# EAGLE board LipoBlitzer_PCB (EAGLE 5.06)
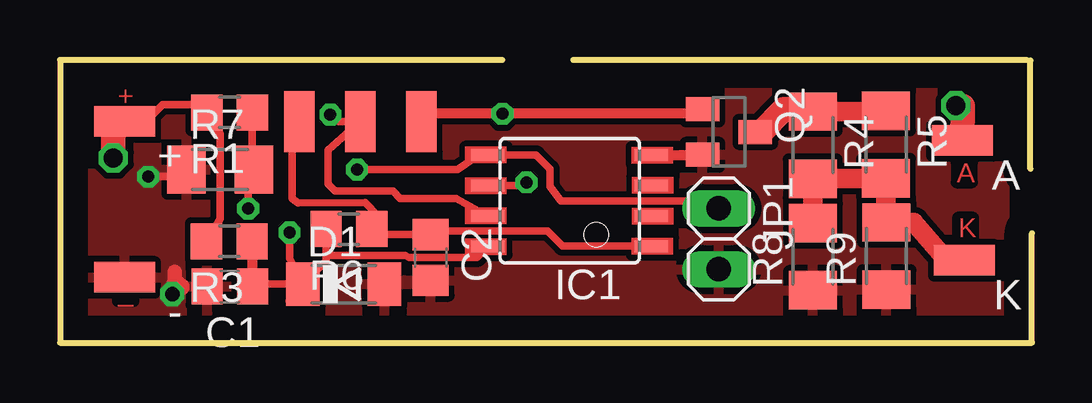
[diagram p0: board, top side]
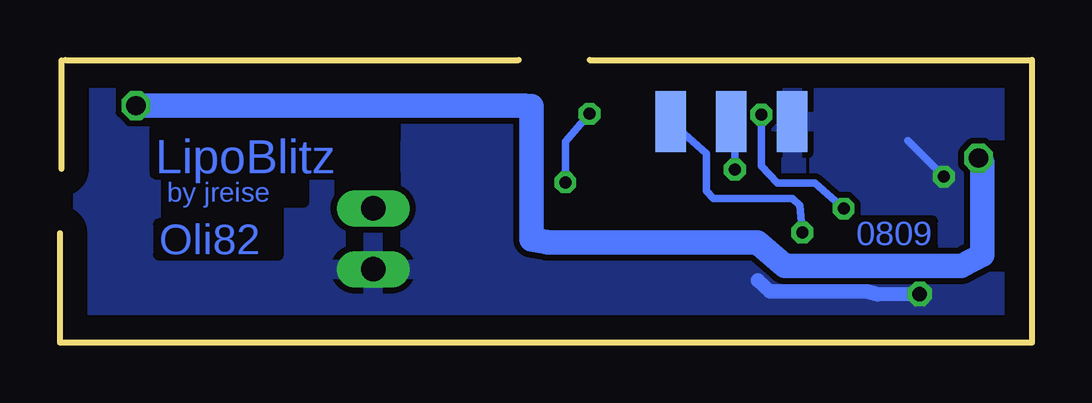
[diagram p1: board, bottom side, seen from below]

Size 40.52 x 11.8 mm. Coordinates in mm from the lower left corner, seen from the top.
Outline: 40.51,0 0,0 0,11.8
Outline: 40.29,11.8 21.4,11.8
Outline: 40.52,0.04 40.52,4.56
Outline: 18.44,11.8 0.01,11.8
Outline: 40.45,7.26 40.45,11.78
Copper layers (1*16): Top 0.035mm / dielectric 1.5mm / Bottom 0.035mm
Design rules "default": minimum track width 10mil, minimum drill 24mil, track to track 8mil, track to pad 8mil, pad to pad 8mil, via to via 8mil, smd to smd 8mil, copper to edge 40mil, drill to drill 8mil, minimum pad ring 10mil, minimum via ring 8mil, stop-mask expansion 4mil, vias tented up to drill 0mil, thermal gap 10mil

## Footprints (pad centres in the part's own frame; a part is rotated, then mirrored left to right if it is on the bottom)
SMD1,27-2,54 = smd 1.27 x 2.54: 1 0,0
C0805 = smd 1.3 x 1.5: 1 -0.95,0; 2 0.95,0
SOD80C = smd 1.4 x 1.8: A 1.7,0; C -1.7,0
8S2 = smd 0.5 x 1.4: 1 -1.905,-3.404; 2 -0.645,-3.404; 3 0.625,-3.404; 4 1.895,-3.404; 5 1.905,3.404; 6 0.635,3.404; 7 -0.635,3.404; 8 -1.905,3.404
1X02 = drill 1.016 long: 1 -1.27,0; 2 1.27,0
SOT23 = smd 1 x 1.4: 1 -0.95,-1.1; 2 0.95,-1.1; 3 0,1.1
R0805 = smd 1.3 x 1.5: 1 -0.95,0; 2 0.95,0
M1206 = smd 1.6 x 2: 1 -1.4,0; 2 1.4,0
MA03-2EDGE = smd 2.54 x 1.27: 1 0,0; 3 0,2.54; 5 0,5.08 | smd 2.54 x 1.27 bottom: 2 0,0; 4 0,2.54; 6 0,5.08

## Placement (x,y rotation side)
+  WIREPADSMD1,27-254  [SMD1,27-2,54]  2.7,9.25 90 top
-  WIREPADSMD1,27-254  [SMD1,27-2,54]  2.7,2.74 90 top
A  WIREPADSMD1,27-254  [SMD1,27-2,54]  37.62,8.44 90 top
C1  100µF  [C0805]  7.09,2.35 180 top
C2  100µF  [C0805]  15.46,3.56 270 top
D1  Z 5.1  [SOD80C]  11.83,2.45 0 top
IC1  TINY13-20SU  [8S2]  21.24,5.93 90 top
JP1  [1X02]  27.46,4.34 270 top
K  WIREPADSMD1,27-254  [SMD1,27-2,54]  37.7,3.44 90 top
Q2  IRLML2502  [SOT23]  27.89,8.8 270 top
R1  68k  [R0805]  7.07,9.61 180 top
R3  4k7  [R0805]  7.06,4.24 180 top
R4  30R  [M1206]  31.38,8.25 270 top
R5  30R  [M1206]  34.43,8.27 270 top
R6  10k  [R0805]  12.05,4.74 180 top
R7  4k7  [M1206]  6.68,7.23 0 top
R8  200R  [M1206]  31.39,3.59 90 top
R9  200R  [M1206]  34.45,3.62 90 top
U$1  MA02-3  [MA03-2EDGE]  15.07,9.22 90 top

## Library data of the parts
+ - A K = wirepad
C1 C2 R1 R3-R9 = rcl
D1 = diode
IC1 = atmel
JP1 = pinhead
Q2 = transistor-small-signal
U$1 = akku

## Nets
GND: -.1 C1.2 C2.2 D1.A IC1.4 JP1.2 Q2.2 R7.1 R8.1 R9.1 U$1.6
N$2: IC1.5 JP1.1 U$1.4
N$3: C1.1 D1.C IC1.8 R3.1 R6.2 U$1.2
N$4: Q2.3 R4.1 R5.1
N$5: IC1.6 Q2.1 U$1.1
N$7: K.1 R4.2 R5.2 R8.2 R9.2
N$10: IC1.7 R1.1 R7.2 U$1.3
N$11: C2.1 IC1.1 R6.1 U$1.5
VCC: +.1 A.1 R1.2 R3.2

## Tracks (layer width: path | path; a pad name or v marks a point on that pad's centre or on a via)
GND  (via drill 0.5, 0.6)
  Top 0.305: R7.1 4.98,6.93 v3.68,6.93
  Top 0.406: IC1.4 26.76,7.82 Q2.2
  Top 0.61: v4.68,2.03 4.65,2.03 4.65,1.9 4.76,1.9 4.76,1.84 4.74,1.84 4.74,2.49 4.93,2.49 4.93,2.23 4.79,2.23 4.79,2.6 | 4.79,2.6 4.79,2.95 | 4.79,2.6 5.1,2.29 5.1,2.37 5.09,2.38
  Bottom 0.305: v3.68,6.93 5.18,8.43
  Bottom 0.61: v4.68,2.03 6.42,2.01 6.88,2.14 10.93,2.14 11.42,2.6
  pour Top (isolate 0.254): 0.9,10.83 0.98,1.06 39.43,1.12 39.35,10.89
  pour Bottom (isolate 0.254): 1,11.03 39.9,11.03 39.9,9.49 39.87,9.49 39.87,1.01 0.92,1.01 0.92,10.95
N$2  (via drill 0.5)
  Top 0.305: v12.38,7.23 16.58,7.23 17.24,7.7 IC1.5 19.85,7.83 20.43,7.25 20.43,6.52 20.88,5.91 27,5.91 JP1.1
  Top 0.406: IC1.5 17.37,7.83
  Bottom 0.305: v12.38,7.23 12.38,9.24 12.51,9.24 U$1.4
N$3  (via drill 0.5)
  Top 0.305: 8.14,2.45 9.6,2.45 | 11.1,3.75 11.1,3.42 D1.C 9.57,3.51 v9.56,4.6 | 11.1,3.75 R6.2 | 11.1,3.75 11.2,3.64 14.39,3.64 14.56,3.55 15.33,3.55 16.21,3.57 17.38,3.57 IC1.8
  Top 0.406: 10.03,2.35 D1.C 9.6,2.45 9.6,1.75 | R3.1 8.04,4.39 C1.1 8.14,2.45
  Bottom 0.305: U$1.2 13.58,7.9 13.58,6.33 13.28,6.03 9.98,6.03 9.68,5.73 v9.56,4.6
N$4
  Top 0.406: 29.23,8.8 Q2.3
  Top 0.813: 31.26,9.74 R4.1 34.4,9.65 R5.1
  Top 1.016: 29.23,8.8 30.18,9.74 31.26,9.74
N$5  (via drill 0.5)
  Top 0.305: U$1.1 15.22,9.23 15.57,9.57 | 26.61,9.57 Q2.1 | IC1.6 19.1,6.56 v19.45,6.7 | v18.44,9.56 18.44,9.57 18.61,9.57
  Top 0.406: 15.57,9.57 18.61,9.57 26.61,9.57
  Bottom 0.305: v19.45,6.7 19.45,8.4 v18.44,9.56
N$7
  Top 0.813: R8.2 31.38,4.81 R4.2 34.64,6.85 R5.2 34.43,4.91 R9.2 35.59,5.02 36.94,3.46 37.68,3.46 K.1
N$10  (via drill 0.5)
  Top 0.305: 12.12,8.87 11.18,8.04 11.18,6.63 11.48,6.33 13.88,6.33 14.18,6.03 16.28,6.03 16.51,6.03 IC1.7 | 12.12,8.87 U$1.3 | R1.1 8,7.31 R7.2 7.85,7.01 v7.85,5.6 | 12.09,9.22 12.09,8.95 | 12.09,9.22 12.09,9.23 | 12.09,9.22 11.6,9.22 v11.27,9.52 | 12.09,9.22 12.09,8.9 12.12,8.87
  Bottom 0.305: v11.27,9.52 11.27,7.38 10.61,6.66 9.05,6.66 v7.85,5.6
N$11
  Top 0.305: 9.68,9.08 9.68,6.03 9.92,5.83 12.72,5.84 13.27,5.28 13.35,4.71 13.38,4.51 15.44,4.53 | C2.1 15.93,4.51 16.1,4.67 20.32,4.67 20.95,4.03 IC1.1
  Top 0.406: 9.68,9.08 U$1.5 | 15.44,4.53 C2.1 | R6.1 13.31,4.66 13.35,4.71
VCC  (via drill 0.8)
  Top 0.305: 3.68,9.33 4.28,9.93 6.07,9.93 | R3.2 6.68,5.17 6.68,8.73 6.1,9.31 R1.2
  Top 0.406: +.1 3.68,9.25 3.68,9.33 | 6.07,9.93 R1.2
  Top 1.016: A.1 37.64,9.87 v37.35,9.89 | v2.22,7.7 2.22,8.77 +.1
  Bottom 0.61: 20.19,4.19 20.24,4.2
  Bottom 1.016: v37.35,9.89 21.14,9.89 20.85,9.87 20.85,4.31 20.24,4.2 | v2.22,7.7 2.06,7.54 2.06,3.68 2.93,3.22 10.3,3.22 11.44,4.19 20.19,4.19
(copper drawn outside any net)
  shapes: Top area x8

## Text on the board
Top: + | A | K | _
Bottom: LipoBlitz | by jreise | 0809 | Oli82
